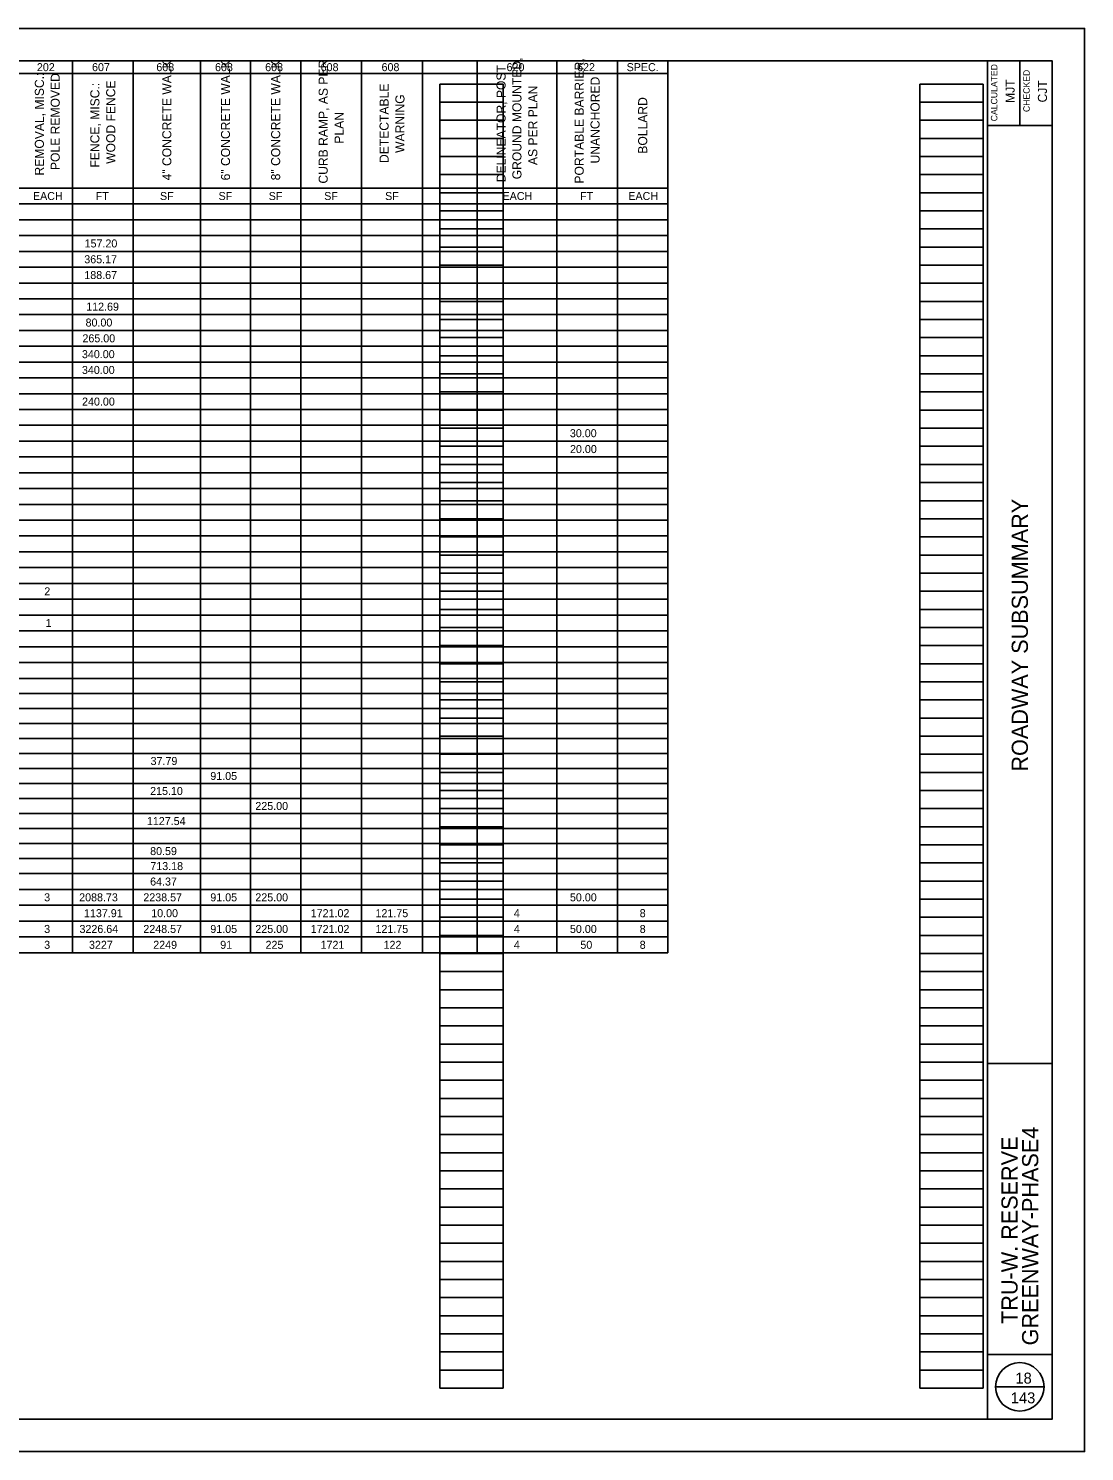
# Model space of a CAD drawing. Extents: x -16 to 102, y -13 to 9.
# Drawn here: x 40.05 to 56.37, y -12.91 to 9.09 of the extents above; entities that cross this region are included whole.
import ezdxf

# ---------------------------------------------------------------- set-up
doc = ezdxf.new("R2010")
doc.units = 0
for name, color, linetype in [('SH_Border', 7, 'Continuous'), ('SH_Cut_Line', 7, 'Continuous'), ('SH_Data', 7, 'Continuous'), ('TX_P_1', 7, 'Continuous')]:
    doc.layers.add(name, color=color, linetype=linetype)

msp = doc.modelspace()

# ---------------------------------------------------------------- linework, layer by layer
at = {"layer": 'SH_Border'}
for p, q in [((54.868, -12.407), (54.868, 8.593)), ((55.368, 8.593), (55.368, 7.593)), ((54.868, 7.593), (55.868, 7.593)), ((54.868, -6.907), (55.868, -6.907)), ((54.868, -11.407), (55.868, -11.407))]:
    msp.add_line(p, q, dxfattribs=at)
msp.add_lwpolyline([(24.368, 8.593), (55.868, 8.593), (55.868, -12.407), (24.368, -12.407)], close=True, dxfattribs=at)
at = {"layer": 'SH_Cut_Line'}
msp.add_lwpolyline([(22.368, -12.907), (56.368, -12.907), (56.368, 9.093), (22.368, 9.093)], close=True, dxfattribs=at)
at = {"layer": 'SH_Data'}
for p, q in [((46.402, -11.927), (46.402, 8.233)), ((46.402, 8.233), (47.382, 8.233)), ((47.382, -11.927), (47.382, 8.233)), ((53.822, -11.927), (53.822, 8.233)), ((53.822, 8.233), (54.802, 8.233)), ((54.802, -11.927), (54.802, 8.233)), ((46.402, 7.953), (47.382, 7.953)), ((53.822, 7.953), (54.802, 7.953)), ((46.402, 7.673), (47.382, 7.673)), ((53.822, 7.673), (54.802, 7.673)), ((46.402, 7.393), (47.382, 7.393)), ((53.822, 7.393), (54.802, 7.393)), ((46.402, 7.113), (47.382, 7.113)), ((53.822, 7.113), (54.802, 7.113)), ((46.402, 6.833), (47.382, 6.833)), ((53.822, 6.833), (54.802, 6.833)), ((46.402, 6.553), (47.382, 6.553)), ((53.822, 6.553), (54.802, 6.553)), ((46.402, 6.273), (47.382, 6.273)), ((53.822, 6.273), (54.802, 6.273)), ((46.402, 5.993), (47.382, 5.993)), ((53.822, 5.993), (54.802, 5.993)), ((46.402, 5.713), (47.382, 5.713)), ((53.822, 5.713), (54.802, 5.713)), ((46.402, 5.433), (47.382, 5.433)), ((53.822, 5.433), (54.802, 5.433)), ((46.402, 5.153), (47.382, 5.153)), ((53.822, 5.153), (54.802, 5.153)), ((46.402, 4.873), (47.382, 4.873)), ((53.822, 4.873), (54.802, 4.873)), ((46.402, 4.593), (47.382, 4.593)), ((53.822, 4.593), (54.802, 4.593)), ((46.402, 4.313), (47.382, 4.313)), ((53.822, 4.313), (54.802, 4.313)), ((46.402, 4.033), (47.382, 4.033)), ((53.822, 4.033), (54.802, 4.033)), ((46.402, 3.753), (47.382, 3.753)), ((53.822, 3.753), (54.802, 3.753)), ((46.402, 3.473), (47.382, 3.473)), ((53.822, 3.473), (54.802, 3.473)), ((46.402, 3.193), (47.382, 3.193)), ((53.822, 3.193), (54.802, 3.193)), ((46.402, 2.913), (47.382, 2.913)), ((53.822, 2.913), (54.802, 2.913)), ((46.402, 2.633), (47.382, 2.633)), ((53.822, 2.633), (54.802, 2.633)), ((46.402, 2.353), (47.382, 2.353)), ((53.822, 2.353), (54.802, 2.353)), ((46.402, 2.073), (47.382, 2.073)), ((53.822, 2.073), (54.802, 2.073)), ((46.402, 1.793), (47.382, 1.793)), ((53.822, 1.793), (54.802, 1.793)), ((46.402, 1.513), (47.382, 1.513)), ((53.822, 1.513), (54.802, 1.513)), ((46.402, 1.233), (47.382, 1.233)), ((53.822, 1.233), (54.802, 1.233)), ((46.402, 0.953), (47.382, 0.953)), ((53.822, 0.953), (54.802, 0.953)), ((46.402, 0.673), (47.382, 0.673)), ((53.822, 0.673), (54.802, 0.673)), ((46.402, 0.393), (47.382, 0.393)), ((53.822, 0.393), (54.802, 0.393)), ((46.402, 0.113), (47.382, 0.113)), ((53.822, 0.113), (54.802, 0.113)), ((46.402, -0.167), (47.382, -0.167)), ((53.822, -0.167), (54.802, -0.167)), ((46.402, -0.447), (47.382, -0.447)), ((53.822, -0.447), (54.802, -0.447)), ((46.402, -0.727), (47.382, -0.727)), ((53.822, -0.727), (54.802, -0.727)), ((46.402, -1.007), (47.382, -1.007)), ((53.822, -1.007), (54.802, -1.007)), ((46.402, -1.287), (47.382, -1.287)), ((53.822, -1.287), (54.802, -1.287)), ((46.402, -1.567), (47.382, -1.567)), ((53.822, -1.567), (54.802, -1.567)), ((46.402, -1.847), (47.382, -1.847)), ((53.822, -1.847), (54.802, -1.847)), ((46.402, -2.127), (47.382, -2.127)), ((53.822, -2.127), (54.802, -2.127)), ((46.402, -2.407), (47.382, -2.407)), ((53.822, -2.407), (54.802, -2.407)), ((46.402, -2.687), (47.382, -2.687)), ((53.822, -2.687), (54.802, -2.687)), ((46.402, -2.967), (47.382, -2.967)), ((53.822, -2.967), (54.802, -2.967)), ((46.402, -3.247), (47.382, -3.247)), ((53.822, -3.247), (54.802, -3.247)), ((46.402, -3.527), (47.382, -3.527)), ((53.822, -3.527), (54.802, -3.527)), ((46.402, -3.807), (47.382, -3.807)), ((53.822, -3.807), (54.802, -3.807)), ((46.402, -4.087), (47.382, -4.087)), ((53.822, -4.087), (54.802, -4.087)), ((46.402, -4.367), (47.382, -4.367)), ((53.822, -4.367), (54.802, -4.367)), ((46.402, -4.647), (47.382, -4.647)), ((53.822, -4.647), (54.802, -4.647)), ((46.402, -4.927), (47.382, -4.927)), ((53.822, -4.927), (54.802, -4.927)), ((46.402, -5.207), (47.382, -5.207)), ((53.822, -5.207), (54.802, -5.207)), ((46.402, -5.487), (47.382, -5.487)), ((53.822, -5.487), (54.802, -5.487)), ((46.402, -5.767), (47.382, -5.767)), ((53.822, -5.767), (54.802, -5.767)), ((46.402, -6.047), (47.382, -6.047)), ((53.822, -6.047), (54.802, -6.047)), ((46.402, -6.327), (47.382, -6.327)), ((53.822, -6.327), (54.802, -6.327)), ((46.402, -6.607), (47.382, -6.607)), ((53.822, -6.607), (54.802, -6.607)), ((46.402, -6.887), (47.382, -6.887)), ((53.822, -6.887), (54.802, -6.887)), ((46.402, -7.167), (47.382, -7.167)), ((53.822, -7.167), (54.802, -7.167)), ((46.402, -7.447), (47.382, -7.447)), ((53.822, -7.447), (54.802, -7.447)), ((46.402, -7.727), (47.382, -7.727)), ((53.822, -7.727), (54.802, -7.727)), ((46.402, -8.007), (47.382, -8.007)), ((53.822, -8.007), (54.802, -8.007)), ((46.402, -8.287), (47.382, -8.287)), ((53.822, -8.287), (54.802, -8.287)), ((46.402, -8.567), (47.382, -8.567)), ((53.822, -8.567), (54.802, -8.567)), ((46.402, -8.847), (47.382, -8.847)), ((53.822, -8.847), (54.802, -8.847)), ((46.402, -9.127), (47.382, -9.127)), ((53.822, -9.127), (54.802, -9.127)), ((46.402, -9.407), (47.382, -9.407)), ((53.822, -9.407), (54.802, -9.407)), ((46.402, -9.687), (47.382, -9.687)), ((53.822, -9.687), (54.802, -9.687)), ((46.402, -9.967), (47.382, -9.967)), ((53.822, -9.967), (54.802, -9.967)), ((46.402, -10.247), (47.382, -10.247)), ((53.822, -10.247), (54.802, -10.247)), ((46.402, -10.527), (47.382, -10.527)), ((53.822, -10.527), (54.802, -10.527)), ((46.402, -10.807), (47.382, -10.807)), ((53.822, -10.807), (54.802, -10.807)), ((46.402, -11.087), (47.382, -11.087)), ((53.822, -11.087), (54.802, -11.087)), ((46.402, -11.367), (47.382, -11.367)), ((53.822, -11.367), (54.802, -11.367)), ((46.402, -11.647), (47.382, -11.647)), ((53.822, -11.647), (54.802, -11.647)), ((46.402, -11.927), (47.382, -11.927)), ((53.822, -11.927), (54.802, -11.927)), ((54.993, -11.907), (55.743, -11.907))]:
    msp.add_line(p, q, dxfattribs=at)
msp.add_circle((55.368, -11.907), 0.375, dxfattribs=at)
at = {"layer": 'TX_P_1'}
for p, q in [((24.368, 8.593), (49.926, 8.593)), ((40.724, 8.593), (40.724, -5.195)), ((41.665, 8.593), (41.665, -5.195)), ((42.703, 8.593), (42.703, -5.195)), ((43.478, 8.593), (43.478, -5.195)), ((44.253, 8.593), (44.253, -5.195)), ((45.194, 8.593), (45.194, -5.195)), ((46.135, 8.593), (46.135, -5.195)), ((46.979, 8.593), (46.979, -5.195)), ((48.21, 8.593), (48.21, -5.195)), ((49.151, 8.593), (49.151, -5.195)), ((49.926, 8.593), (49.926, -5.195)), ((31.896, 8.397), (49.926, 8.397)), ((31.896, 6.625), (49.926, 6.625)), ((24.368, 6.381), (49.926, 6.381)), ((24.368, 6.136), (49.926, 6.136)), ((24.368, 5.892), (49.926, 5.892)), ((24.368, 5.647), (49.926, 5.647)), ((24.368, 5.403), (49.926, 5.403)), ((24.368, 5.158), (49.926, 5.158)), ((24.368, 4.914), (49.926, 4.914)), ((24.368, 4.669), (49.926, 4.669)), ((24.368, 4.425), (49.926, 4.425)), ((24.368, 4.18), (49.926, 4.18)), ((24.368, 3.936), (49.926, 3.936)), ((24.368, 3.691), (49.926, 3.691)), ((24.368, 3.447), (49.926, 3.447)), ((24.368, 3.202), (49.926, 3.202)), ((24.368, 2.958), (49.926, 2.958)), ((24.368, 2.714), (49.926, 2.714)), ((24.368, 2.469), (49.926, 2.469)), ((24.368, 2.225), (49.926, 2.225)), ((24.368, 1.98), (49.926, 1.98)), ((24.368, 1.736), (49.926, 1.736)), ((24.368, 1.491), (49.926, 1.491)), ((24.368, 1.247), (49.926, 1.247)), ((24.368, 1.002), (49.926, 1.002)), ((24.368, 0.758), (49.926, 0.758)), ((24.368, 0.513), (49.926, 0.513)), ((24.368, 0.269), (49.926, 0.269)), ((24.368, 0.024), (49.926, 0.024)), ((24.368, -0.22), (49.926, -0.22)), ((24.368, -0.465), (49.926, -0.465)), ((24.368, -0.709), (49.926, -0.709)), ((24.368, -0.954), (49.926, -0.954)), ((24.368, -1.186), (49.926, -1.186)), ((24.368, -1.418), (49.926, -1.418)), ((24.368, -1.65), (49.926, -1.65)), ((24.368, -1.882), (49.926, -1.882)), ((24.368, -2.115), (49.926, -2.115)), ((24.368, -2.347), (49.926, -2.347)), ((24.368, -2.579), (49.926, -2.579)), ((24.368, -2.811), (49.926, -2.811)), ((24.368, -3.044), (49.926, -3.044)), ((24.368, -3.276), (49.926, -3.276)), ((24.368, -3.508), (49.926, -3.508)), ((24.368, -3.74), (49.926, -3.74)), ((24.368, -3.973), (49.926, -3.973)), ((24.368, -4.217), (49.926, -4.217)), ((24.368, -4.462), (49.926, -4.462)), ((24.368, -4.706), (49.926, -4.706)), ((24.368, -4.951), (49.926, -4.951)), ((24.368, -5.195), (49.926, -5.195))]:
    msp.add_line(p, q, dxfattribs=at)

# ---------------------------------------------------------------- texts
at = {"layer": 'SH_Data'}
for s, height, p in [('CALCULATED', 0.1, (55.021, 7.658)), ('CHECKED', 0.1, (55.521, 7.801)), ('MJT', 0.14, (55.288, 7.942)), ('CJT', 0.14, (55.788, 7.949)), ('ROADWAY SUBSUMMARY', 0.25, (55.493, -2.395)), ('GREENWAY-PHASE4', 0.25, (55.653, -11.266)), ('TRU-W. RESERVE', 0.25, (55.334, -10.934))]:
    msp.add_text(s, height=height, rotation=90, dxfattribs=at).set_placement(p)
msp.add_text('143', height=0.17, dxfattribs=at).set_placement((55.228, -12.162))
at = {"layer": 'TX_P_1'}
for s, height, p in [('4" CONCRETE WALK', 0.14004, (42.254, 6.744)), ('6" CONCRETE WALK', 0.14004, (43.161, 6.744)), ('8" CONCRETE WALK', 0.14004, (43.936, 6.745)), ('CURB RAMP, AS PER', 0.14004, (44.671, 6.695)), ('GROUND MOUNTED,', 0.14004, (47.665, 6.761)), ('PORTABLE BARRIER,', 0.14004, (48.628, 6.695)), ('REMOVAL, MISC.:', 0.14004, (40.284, 6.819)), ('POLE REMOVED', 0.14004, (40.529, 6.904)), ('DELINEATOR, POST', 0.14004, (47.42, 6.716)), ('FENCE, MISC.:', 0.14004, (41.142, 6.942)), ('WOOD FENCE', 0.14, (41.387, 7)), ('DETECTABLE', 0.14, (45.612, 7.013)), ('AS PER PLAN', 0.14004, (47.91, 6.981)), ('UNANCHORED', 0.14, (48.873, 7.006)), ('WARNING', 0.14, (45.857, 7.169)), ('BOLLARD', 0.14, (49.609, 7.157)), ('PLAN', 0.14, (44.916, 7.312))]:
    msp.add_text(s, height=height, rotation=90, dxfattribs=at).set_placement(p)
for s, height, p in [('202', 0.1237, (40.176, 8.433)), ('607', 0.1237, (41.028, 8.433)), ('608', 0.1237, (42.022, 8.433)), ('608', 0.1237, (42.929, 8.433)), ('608', 0.1237, (43.704, 8.433)), ('608', 0.1237, (44.562, 8.433)), ('608', 0.1237, (45.503, 8.433)), ('620', 0.1237, (47.435, 8.433)), ('622', 0.1237, (48.525, 8.433)), ('SPEC.', 0.1237, (49.291, 8.433)), ('EACH', 0.1237, (40.115, 6.441)), ('FT', 0.1237, (41.085, 6.441)), ('SF', 0.1237, (42.078, 6.441)), ('SF', 0.1237, (42.984, 6.441)), ('SF', 0.1237, (43.759, 6.441)), ('SF', 0.1237, (44.617, 6.441)), ('SF', 0.1237, (45.558, 6.441)), ('EACH', 0.1237, (47.373, 6.441)), ('FT', 0.1237, (48.571, 6.441)), ('EACH', 0.1237, (49.317, 6.441)), ('157.20', 0.1237, (40.913, 5.708)), ('365.17', 0.1237, (40.908, 5.463)), ('188.67', 0.1237, (40.909, 5.219)), ('112.69', 0.1237, (40.938, 4.73)), ('80.00', 0.1237, (40.928, 4.485)), ('265.00', 0.1237, (40.88, 4.241)), ('340.00', 0.1237, (40.872, 3.996)), ('340.00', 0.1237, (40.872, 3.752)), ('240.00', 0.1237, (40.874, 3.263)), ('30.00', 0.1237, (48.414, 2.774)), ('20.00', 0.1237, (48.416, 2.529)), ('2', 0.124, (40.29, 0.329)), ('1', 0.124, (40.311, -0.16)), ('37.79', 0.1237, (41.933, -2.293)), ('91.05', 0.1237, (42.856, -2.525)), ('215.10', 0.1237, (41.926, -2.757)), ('225.00', 0.1237, (43.552, -2.989)), ('1127.54', 0.1237, (41.876, -3.222)), ('80.59', 0.1237, (41.926, -3.686)), ('713.18', 0.1237, (41.929, -3.918)), ('64.37', 0.1237, (41.926, -4.157)), ('3', 0.124, (40.288, -4.401)), ('2088.73', 0.1237, (40.829, -4.401)), ('2238.57', 0.1237, (41.821, -4.401)), ('91.05', 0.1237, (42.856, -4.401)), ('225.00', 0.1237, (43.552, -4.401)), ('50.00', 0.1237, (48.415, -4.401)), ('1137.91', 0.1237, (40.904, -4.646)), ('10.00', 0.1237, (41.943, -4.646)), ('1721.02', 0.1237, (44.408, -4.646)), ('121.75', 0.1237, (45.409, -4.646)), ('4', 0.124, (47.548, -4.646)), ('8', 0.124, (49.493, -4.646)), ('3', 0.124, (40.288, -4.89)), ('3226.64', 0.1237, (40.834, -4.89)), ('2248.57', 0.1237, (41.821, -4.89)), ('91.05', 0.1237, (42.856, -4.89)), ('225.00', 0.1237, (43.552, -4.89)), ('1721.02', 0.1237, (44.408, -4.89)), ('121.75', 0.1237, (45.409, -4.89)), ('4', 0.124, (47.548, -4.89)), ('50.00', 0.1237, (48.415, -4.89)), ('8', 0.124, (49.493, -4.89)), ('3', 0.124, (40.288, -5.135)), ('3227', 0.1237, (40.981, -5.135)), ('2249', 0.1237, (41.974, -5.135)), ('91', 0.1237, (43.009, -5.135)), ('225', 0.1237, (43.71, -5.135)), ('1721', 0.1237, (44.56, -5.135)), ('122', 0.1237, (45.534, -5.135)), ('4', 0.124, (47.548, -5.135)), ('50', 0.1237, (48.576, -5.135)), ('8', 0.124, (49.493, -5.135)), ('18', 0.17, (55.3, -11.857))]:
    msp.add_text(s, height=height, dxfattribs=at).set_placement(p)

doc.saveas('drawing.dxf')
